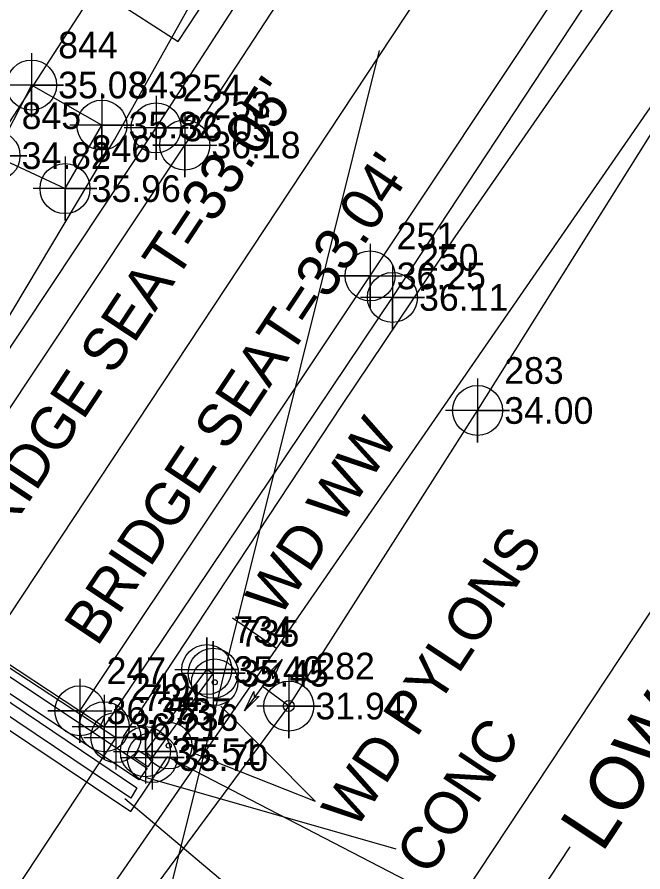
# Model space of a CAD drawing. Extents: x 2603627 to 2605187, y 896619 to 899063.
# Drawn here: x 2604564.9 to 2604623.6, y 898167.5 to 898247.7 of the extents above; entities that cross this region are included whole.
import ezdxf

# ---------------------------------------------------------------- set-up
doc = ezdxf.new("R2010")
doc.units = 0
for name, color, linetype in [('Default Symbol Leader', 7, 'Continuous'), ('Default Symbol Text', 7, 'Continuous'), ('Exist Guardrail', 7, 'Continuous'), ('Exist Horizontal Alignment', 7, 'Continuous'), ('Exist Horizontal Baseline Alignment', 7, 'Continuous'), ('Exist Horizontal Baseline Alignment Tick small', 7, 'Continuous'), ('Exist Hydro Jurisdictional Stream or Body of Water', 7, 'Continuous'), ('Exist Hydro Stream or Body of Water', 7, 'Continuous'), ('Exist Other Culture Area Outline', 7, 'Continuous'), ('Exist Other Culture Area Outline Cogo Elevation', 7, 'Continuous'), ('Exist Other Culture Area Outline Cogo Number', 7, 'Continuous'), ('Exist Other Culture Area Outline Cogo Point CELL', 7, 'Continuous'), ('Exist Other Culture Located Object CELL', 7, 'Continuous'), ('Exist Other Culture Located Object Leader', 7, 'Continuous'), ('Exist Other Culture Located Object Text', 7, 'Continuous'), ('Exist Property Tie Line', 7, 'Continuous'), ('Exist Right of Way Line', 7, 'Continuous'), ('Exist Roads EOP', 7, 'Continuous'), ('Exist Roads EOP Cogo Elevation', 7, 'Continuous'), ('Exist Roads EOP Cogo Number', 7, 'Continuous'), ('Exist Roads EOP Cogo Point CELL', 7, 'Continuous'), ('Exist Roads EOT', 7, 'Continuous'), ('Exist Roads EOT Cogo Elevation', 7, 'Continuous'), ('Exist Roads EOT Cogo Number', 7, 'Continuous'), ('Exist Roads EOT Cogo Point CELL', 7, 'Continuous'), ('Exist Structure Major Bridge Seat Top Elevation', 7, 'Continuous'), ('Exist Structure Major Bridge Topo', 7, 'Continuous'), ('Exist Structure Major Bridge Topo Leader', 7, 'Continuous'), ('Exist Structure Major Bridge WW', 7, 'Continuous'), ('Exist Structure Major Bridge WW Cogo Elevation', 7, 'Continuous'), ('Exist Structure Major Bridge WW Cogo Number', 7, 'Continuous'), ('Exist Structure Major Bridge WW Cogo Point CELL', 7, 'Continuous'), ('Exist Structure Major Bridge WW Leader', 7, 'Continuous'), ('Exist Structure Major Bridge WW Text', 7, 'Continuous'), ('Exist Structure Major Deck Tunnel Box Culvert', 7, 'Continuous'), ('Exist Structure Major Deck Tunnel Box Culvert Cogo Number', 7, 'Continuous'), ('Exist Structure Major Deck Tunnel Box Culvert Cogo Point CELL', 7, 'Continuous'), ('Exist Utilities Telephone UG Cable SUE LOS C', 7, 'Continuous'), ('Exist Utilities Telephone UG FO SUE LOS C', 7, 'Continuous'), ('Exist Utilities Water Change of Service SUE CELL', 7, 'Continuous'), ('Exist Utilities Water UG Line SUE LOS B', 7, 'Continuous'), ('Exist Utilities Water UG Line SUE LOS B Cogo Elevation', 7, 'Continuous'), ('Exist Utilities Water UG Line SUE LOS B Cogo Number', 7, 'Continuous'), ('Exist Utilities Water UG Line SUE LOS B Cogo Point CELL', 7, 'Continuous'), ('Exist Utilities Water UG Line SUE LOS C', 7, 'Continuous')]:
    doc.layers.add(name, color=color, linetype=linetype)

# ---------------------------------------------------------------- blocks, each defined once
blk = doc.blocks.new('EXIST ROADS EOP COGO POINT')
at = {"layer": 'Exist Roads EOP Cogo Point CELL'}
blk.add_lwpolyline([(0, 0.06), (0, -0.06), (0, 0), (0.06, 0), (-0.06, 0)], dxfattribs=at)
blk.add_circle((0, 0), 0.0469, dxfattribs=at)
blk = doc.blocks.new('EXIST ROADS EOT COGO POINT')
at = {"layer": 'Exist Roads EOT Cogo Point CELL'}
blk.add_lwpolyline([(0, 0.06), (0, -0.06), (0, 0), (-0.06, 0), (0.06, 0)], dxfattribs=at)
blk.add_circle((0, 0), 0.0469, dxfattribs=at)
blk = doc.blocks.new('EXIST UTILITIES WATER UG LINE SUE LOS B COGO POINT')
at = {"layer": 'Exist Utilities Water UG Line SUE LOS B Cogo Point CELL'}
blk.add_lwpolyline([(0, 0.06), (0, -0.06), (0, 0), (0.06, 0), (-0.06, 0)], dxfattribs=at)
blk.add_circle((0, 0), 0.0469, dxfattribs=at)
blk = doc.blocks.new('EXIST STRUCTURE MAJOR DECK TUNNEL BOX CULVERT COGO POINT')
at = {"layer": 'Exist Structure Major Deck Tunnel Box Culvert Cogo Point CELL'}
blk.add_lwpolyline([(-0.06, 0), (0.06, 0), (0, 0), (0, 0.06), (0, -0.06)], dxfattribs=at)
blk.add_circle((0, 0), 0.0469, dxfattribs=at)
blk = doc.blocks.new('EXIST STRUCTURE MAJOR BRIDGE WW COGO POINT')
at = {"layer": 'Exist Structure Major Bridge WW Cogo Point CELL'}
blk.add_lwpolyline([(-0.06, 0), (0.06, 0), (0, 0), (0, 0.06), (0, -0.06)], dxfattribs=at)
blk.add_circle((0, 0), 0.0469, dxfattribs=at)
blk = doc.blocks.new('EXIST OTHER CULTURE AREA OUTLINE COGO POINT')
at = {"layer": 'Exist Other Culture Area Outline Cogo Point CELL'}
blk.add_lwpolyline([(0, 0.06), (0, -0.06), (0, 0), (0.06, 0), (-0.06, 0)], dxfattribs=at)
blk.add_circle((0, 0), 0.0469, dxfattribs=at)

msp = doc.modelspace()

# ---------------------------------------------------------------- linework, layer by layer
at = {"layer": 'Default Symbol Leader'}
msp.add_line((2604608.764, 898157.759), (2604616.82, 898169.887), dxfattribs=at)
at = {"layer": 'Exist Guardrail'}
for points in [[(2604549.447, 898197.005), (2604551.688, 898200.424), (2604561.034, 898214.376), (2604574.047, 898236.144), (2604583.438, 898252.897), (2604603.34, 898290.06), (2604614.453, 898307.438), (2604661.781, 898380.221)], [(2604631.981, 898264.559), (2604605.99, 898227.058), (2604595.344, 898211.259), (2604574.882, 898180.207)]]:
    msp.add_lwpolyline(points, dxfattribs=at)
at = {"layer": 'Exist Horizontal Alignment'}
msp.add_line((2604537.349, 898151.011), (2604647.762, 898317.915), dxfattribs=at)
at = {"layer": 'Exist Horizontal Baseline Alignment'}
msp.add_line((2604544.961, 898124.436), (2604793.601, 898483.903), dxfattribs=at)
at = {"layer": 'Exist Horizontal Baseline Alignment Tick small'}
msp.add_line((2604589.255, 898188.473), (2604585.142, 898191.317), dxfattribs=at)
at = {"layer": 'Exist Hydro Jurisdictional Stream or Body of Water'}
msp.add_line((2604545.668, 898193.174), (2604572.086, 898175.527), dxfattribs=at)
msp.add_lwpolyline([(2604623.046, 898149.352), (2604608.245, 898161.284), (2604606.782, 898162.463), (2604601.562, 898166.672), (2604579.029, 898178.3)], dxfattribs=at)
at = {"layer": 'Exist Hydro Stream or Body of Water'}
msp.add_lwpolyline([(2604572.086, 898175.527), (2604575.605, 898173.177), (2604579.029, 898178.3)], dxfattribs=at)
at = {"layer": 'Exist Other Culture Area Outline'}
msp.add_lwpolyline([(2604572.88, 898237.533), (2604566.28, 898241.293), (2604562.846, 898234.669), (2604569.416, 898231.58), (2604572.88, 898237.533)], dxfattribs=at)
at = {"layer": 'Exist Other Culture Located Object CELL'}
for centre, radius in [((2604583.466, 898185.307), 2.18), ((2604583.466, 898185.307), 0.24), ((2604579.146, 898179.368), 2.18), ((2604579.146, 898179.368), 0.24)]:
    msp.add_circle(centre, radius, dxfattribs=at)
at = {"layer": 'Exist Other Culture Located Object Leader'}
for p in [(2604584.036, 898183.066), (2604581.494, 898178.673)]:
    msp.add_line(p, (2604592.898, 898174.168), dxfattribs=at)
at = {"layer": 'Exist Property Tie Line'}
msp.add_line((2604598.893, 898244.519), (2604562.447, 898098.35), dxfattribs=at)
at = {"layer": 'Exist Right of Way Line'}
msp.add_line((2604579.05, 898123.424), (2604689.463, 898290.329), dxfattribs=at)
at = {"layer": 'Exist Roads EOP'}
for p, q in [((2604600.141, 898221.379), (2604629.439, 898265.837)), ((2604550.488, 898195.948), (2604577.958, 898237.274)), ((2604573.101, 898181.136), (2604600.141, 898221.379))]:
    msp.add_line(p, q, dxfattribs=at)
for points in [[(2604577.958, 898237.274), (2604606.454, 898281.24), (2604633.893, 898322.503), (2604662.447, 898365.468), (2604690.624, 898408.056), (2604717.287, 898448.088), (2604745.459, 898490.106), (2604773.604, 898532.604), (2604800.879, 898573.951), (2604828.345, 898615.462), (2604855.104, 898656.153), (2604883.526, 898699.093), (2604911.286, 898740.949), (2604939.376, 898783.407), (2604966.332, 898824.04), (2604993.378, 898865.275), (2605022.2, 898908.378), (2605029.463, 898919.464)], [(2604553.09, 898194.244), (2604562.061, 898188.367), (2604570.819, 898182.631), (2604573.101, 898181.136)]]:
    msp.add_lwpolyline(points, dxfattribs=at)
at = {"layer": 'Exist Roads EOT'}
for p, q in [((2604553.101, 898194.261), (2604580.649, 898235.671)), ((2604570.83, 898182.648), (2604598.038, 898223.4))]:
    msp.add_line(p, q, dxfattribs=at)
for points in [[(2604580.649, 898235.671), (2604609.227, 898279.299), (2604636.662, 898320.715), (2604665.181, 898363.913), (2604693.369, 898406.363), (2604719.945, 898446.052), (2604748.005, 898488.337), (2604776.145, 898530.838), (2604803.496, 898572.303), (2604830.948, 898613.912), (2604857.578, 898654.466), (2604886.019, 898697.378), (2604913.857, 898739.329), (2604942.027, 898781.72), (2604969.056, 898822.38), (2604996.07, 898863.439), (2605024.73, 898906.725), (2605032.001, 898917.781)], [(2604598.038, 898223.4), (2604627.235, 898267.233), (2604654.638, 898308.575), (2604683.284, 898352.013), (2604711.268, 898394.145), (2604737.977, 898434.049), (2604766.043, 898475.935), (2604794.958, 898519.255), (2604821.606, 898559.824), (2604848.894, 898601.402), (2604876.121, 898642.728), (2604904.396, 898685.354), (2604932.334, 898727.234), (2604960.287, 898769.489), (2604987.32, 898810.189), (2605014.123, 898850.946), (2605043.077, 898894.886), (2605050.197, 898905.717)]]:
    msp.add_lwpolyline(points, dxfattribs=at)
at = {"layer": 'Exist Structure Major Bridge Topo'}
for p, q in [((2604544.764, 898196.555), (2604576.151, 898175.402)), ((2604575.596, 898174.44), (2604544.128, 898195.556)), ((2604576.151, 898175.402), (2604575.596, 898174.44))]:
    msp.add_line(p, q, dxfattribs=at)
at = {"layer": 'Exist Structure Major Bridge Topo Leader'}
msp.add_line((2604575.03, 898174.404), (2604587.483, 898163.92), dxfattribs=at)
at = {"layer": 'Exist Structure Major Bridge WW'}
for p, q in [((2604545.966, 898197.964), (2604577.11, 898177.246)), ((2604576.346, 898176.142), (2604545.239, 898196.91)), ((2604576.955, 898178.799), (2604582.722, 898186.493)), ((2604583.323, 898186.151), (2604577.605, 898178.25)), ((2604582.722, 898186.493), (2604583.323, 898186.151)), ((2604576.955, 898178.799), (2604577.605, 898178.25)), ((2604577.11, 898177.246), (2604576.346, 898176.142))]:
    msp.add_line(p, q, dxfattribs=at)
msp.add_lwpolyline([(2604577.669, 898178.057), (2604577.2, 898177.378), (2604575.871, 898178.246), (2604576.315, 898178.897), (2604577.669, 898178.057)], dxfattribs=at)
at = {"layer": 'Exist Structure Major Bridge WW Leader'}
msp.add_line((2604576.936, 898176.409), (2604600.462, 898169.701), dxfattribs=at)
at = {"layer": 'Exist Structure Major Deck Tunnel Box Culvert'}
msp.add_lwpolyline([(2604525.453, 898159.692), (2604549.566, 898196.253), (2604574.197, 898180.119), (2604549.896, 898143.345), (2604525.453, 898159.692)], dxfattribs=at)
at = {"layer": 'Exist Utilities Telephone UG Cable SUE LOS C'}
for p, q in [((2604580.043, 898245.374), (2604795.48, 898573.628)), ((2604549.351, 898265.156), (2604580.043, 898245.374))]:
    msp.add_line(p, q, dxfattribs=at)
at = {"layer": 'Exist Utilities Telephone UG FO SUE LOS C'}
msp.add_line((2604555.472, 898224.397), (2604671.199, 898402.262), dxfattribs=at)
at = {"layer": 'Exist Utilities Water Change of Service SUE CELL'}
for p, q in [((2604589.799, 898187.428), (2604586.249, 898182.638)), ((2604587.932, 898184.909), (2604589.799, 898187.428)), ((2604590.411, 898183.072), (2604587.932, 898184.909)), ((2604590.411, 898183.072), (2604590.411, 898183.072))]:
    msp.add_line(p, q, dxfattribs=at)
for points in [[(2604589.799, 898187.428), (2604588.902, 898185.64), (2604588.875, 898186.182), (2604588.403, 898186.057)], [(2604586.249, 898182.638), (2604587.146, 898184.426), (2604587.172, 898183.884), (2604587.645, 898184.009)]]:
    msp.add_lwpolyline(points, close=True, dxfattribs=at)
msp.add_circle((2604590.411, 898183.072), 0.517, dxfattribs=at)
at = {"layer": 'Exist Utilities Water UG Line SUE LOS B'}
msp.add_lwpolyline([(2604590.411, 898183.072), (2604608.125, 898210.782), (2604631.329, 898247.72), (2604631.98, 898248.774), (2604637.931, 898260.896), (2604650.01, 898281.754), (2604670.128, 898312.662), (2604706.143, 898370.49), (2604744.202, 898428.792), (2604775.847, 898478.143), (2604817.618, 898541.222), (2604844.764, 898580.182), (2604876.202, 898627.221), (2604907.55, 898675.151), (2604931.687, 898711.473), (2604963.512, 898758.627), (2604991.084, 898800.904), (2605022.229, 898847.261), (2605044.126, 898880.129), (2605057.71, 898900.736)], dxfattribs=at)
at = {"layer": 'Exist Utilities Water UG Line SUE LOS C'}
msp.add_line((2604550.547, 898129.275), (2604590.411, 898183.072), dxfattribs=at)

# ---------------------------------------------------------------- block references
at = {"layer": 'Exist Other Culture Area Outline Cogo Point CELL', "xscale": 50, "yscale": 50}
for p in [(2604566.28, 898241.293), (2604572.88, 898237.533), (2604562.846, 898234.669), (2604569.416, 898231.58)]:
    msp.add_blockref('EXIST OTHER CULTURE AREA OUTLINE COGO POINT', p, dxfattribs=at)
at = {"layer": 'Exist Roads EOP Cogo Point CELL', "xscale": 50, "yscale": 50}
for p in [(2604577.958, 898237.274), (2604600.141, 898221.379), (2604573.101, 898181.136)]:
    msp.add_blockref('EXIST ROADS EOP COGO POINT', p, dxfattribs=at)
at = {"layer": 'Exist Roads EOT Cogo Point CELL', "xscale": 50, "yscale": 50}
for p in [(2604580.649, 898235.671), (2604598.038, 898223.4), (2604570.819, 898182.631)]:
    msp.add_blockref('EXIST ROADS EOT COGO POINT', p, dxfattribs=at)
at = {"layer": 'Exist Structure Major Bridge WW Cogo Point CELL', "xscale": 50, "yscale": 50}
for p in [(2604582.722, 898186.493), (2604583.323, 898186.151), (2604576.955, 898178.799), (2604577.605, 898178.25)]:
    msp.add_blockref('EXIST STRUCTURE MAJOR BRIDGE WW COGO POINT', p, dxfattribs=at)
at = {"layer": 'Exist Structure Major Deck Tunnel Box Culvert Cogo Point CELL', "xscale": 50, "yscale": 50}
msp.add_blockref('EXIST STRUCTURE MAJOR DECK TUNNEL BOX CULVERT COGO POINT', (2604574.197, 898180.119), dxfattribs=at)
at = {"layer": 'Exist Utilities Water UG Line SUE LOS B Cogo Point CELL', "xscale": 50, "yscale": 50}
for p in [(2604608.125, 898210.782), (2604590.411, 898183.072)]:
    msp.add_blockref('EXIST UTILITIES WATER UG LINE SUE LOS B COGO POINT', p, dxfattribs=at)

# ---------------------------------------------------------------- texts
at = {"layer": 'Default Symbol Text'}
msp.add_text("LOW WIRE=57.54'", height=5, rotation=56.40943, dxfattribs=at).set_placement((2604619.809, 898169.23))
at = {"layer": 'Exist Other Culture Area Outline Cogo Elevation'}
for s, p in [('35.03', (2604568.78, 898240.043)), ('35.82', (2604575.38, 898236.283)), ('34.82', (2604565.346, 898233.419)), ('35.96', (2604571.916, 898230.33))]:
    msp.add_text(s, height=2.5, dxfattribs=at).set_placement(p)
at = {"layer": 'Exist Other Culture Area Outline Cogo Number'}
for s, p in [('844', (2604568.78, 898243.793)), ('843', (2604575.38, 898240.033)), ('845', (2604565.346, 898237.169)), ('846', (2604571.916, 898234.08))]:
    msp.add_text(s, height=2.5, dxfattribs=at).set_placement(p)
at = {"layer": 'Exist Other Culture Located Object Text'}
msp.add_text('WD PYLONS', height=4, rotation=56.47848, dxfattribs=at).set_placement((2604596.638, 898171.35))
at = {"layer": 'Exist Roads EOP Cogo Elevation'}
for s, p in [('36.05', (2604580.459, 898236.024)), ('36.11', (2604602.641, 898220.129)), ('36.21', (2604575.601, 898179.886))]:
    msp.add_text(s, height=2.5, dxfattribs=at).set_placement(p)
at = {"layer": 'Exist Roads EOP Cogo Number'}
for s, p in [('254', (2604580.459, 898239.774)), ('250', (2604602.641, 898223.879)), ('249', (2604575.601, 898183.636))]:
    msp.add_text(s, height=2.5, dxfattribs=at).set_placement(p)
at = {"layer": 'Exist Roads EOT Cogo Elevation'}
for s, p in [('36.18', (2604583.149, 898234.421)), ('36.25', (2604600.538, 898222.15)), ('36.35', (2604573.319, 898181.381))]:
    msp.add_text(s, height=2.5, dxfattribs=at).set_placement(p)
at = {"layer": 'Exist Roads EOT Cogo Number'}
for s, p in [('253', (2604583.149, 898238.171)), ('251', (2604600.538, 898225.9)), ('247', (2604573.319, 898185.131))]:
    msp.add_text(s, height=2.5, dxfattribs=at).set_placement(p)
at = {"layer": 'Exist Structure Major Bridge Seat Top Elevation'}
for s, p in [("BRIDGE SEAT=33.05'", (2604561.73, 898195.662)), ("BRIDGE SEAT=33.04'", (2604572.449, 898188.544))]:
    msp.add_text(s, height=4, rotation=56.40944, dxfattribs=at).set_placement(p)
at = {"layer": 'Exist Structure Major Bridge WW Cogo Elevation'}
for s, p in [('35.40', (2604585.222, 898185.243)), ('35.45', (2604585.823, 898184.901)), ('35.51', (2604579.455, 898177.549)), ('35.70', (2604580.105, 898177))]:
    msp.add_text(s, height=2.5, dxfattribs=at).set_placement(p)
at = {"layer": 'Exist Structure Major Bridge WW Cogo Number'}
for s, p in [('734', (2604585.222, 898188.993)), ('735', (2604585.823, 898188.651)), ('737', (2604579.455, 898181.299)), ('736', (2604580.105, 898180.75))]:
    msp.add_text(s, height=2.5, dxfattribs=at).set_placement(p)
at = {"layer": 'Exist Structure Major Bridge WW Text'}
for s, p in [('WD WW', (2604589.503, 898191.219)), ('CONC', (2604603.574, 898167.014))]:
    msp.add_text(s, height=4, rotation=56.47848, dxfattribs=at).set_placement(p)
at = {"layer": 'Exist Structure Major Deck Tunnel Box Culvert Cogo Number'}
msp.add_text('724', height=2.5, dxfattribs=at).set_placement((2604576.697, 898182.619))
at = {"layer": 'Exist Utilities Water UG Line SUE LOS B Cogo Elevation'}
for s, p in [('34.00', (2604610.625, 898209.532)), ('31.94', (2604592.911, 898181.823))]:
    msp.add_text(s, height=2.5, dxfattribs=at).set_placement(p)
at = {"layer": 'Exist Utilities Water UG Line SUE LOS B Cogo Number'}
for s, p in [('283', (2604610.625, 898213.282)), ('282', (2604592.911, 898185.573))]:
    msp.add_text(s, height=2.5, dxfattribs=at).set_placement(p)

doc.saveas('drawing.dxf')
